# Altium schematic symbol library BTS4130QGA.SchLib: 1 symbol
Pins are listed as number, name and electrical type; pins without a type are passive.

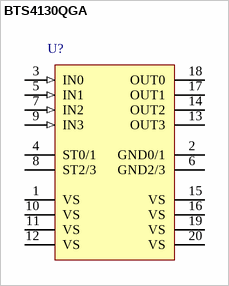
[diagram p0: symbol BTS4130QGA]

## BTS4130QGA
designator U?
Smart High-Side Power Switch, 4 Channels, 1.7 A Load Current, -40 to 150 degC, PG-DSO-20-32, Reel, Green; Manufacturer: Infineon; PartNumber: BTS4130QGA; Channels: 4; Green: TRUE; Group: Automotive Qualified; Load Current (typ): 1.7 A; Ptot (max): 1.4 W; Recommended Operating Voltage Max.: 20 V; Recommended Operating Voltage Min.: 5.5 V; RON @ 25degreesC: 130 mOhm; RON(max) @ 150degreesC: 260 mOhm; toff (max): 270 us; ton (max): 250 us
footprint INF-PG-DSO-20-32_N (SOP, 20-Leads, Body 12.7x7.5mm, Pitch 1.27mm, IPC Medium Density)
footprint INF-PG-DSO-20-32_L (SOP, 20-Leads, Body 12.7x7.5mm, Pitch 1.27mm, IPC High Density)
footprint INF-PG-DSO-20-32_M (SOP, 20-Leads, Body 12.7x7.5mm, Pitch 1.27mm, IPC Low Density)
pins: 1 VS (power) "Battery voltage; Design the wiring for the simultaneous maximum short circuit currents from channel 0 and 1 and also for low thermal resistance", 2 GND0/1 (power) "Ground; Ground connection for channel 0 and 1", 3 IN0 (in) "Input channel 0; Input signal for channel 0. Activate the channel in case of logic high level", 4 ST0/1 (oc) "Diagnostic feedback; of channel 0/1. Open drain.", 5 IN1 (in) "Input channel 1; Input signal for channel 1. Activate the channel in case of logic high level", 6 GND2/3 (power) "Ground; Ground connection for channel 2 and 3", 7 IN2 (in) "Input channel 2; Input signal for channel 2. Activate the channel in case of logic high level", 8 ST2/3 (oc) "Diagnostic feedback; of channel 2/3. Open drain.", 9 IN3 (in) "Input channel 3; Input signal for channel 3. Activate the channel in case of logic high level", 10 VS (power) "Battery voltage; Design the wiring for the simultaneous maximum short circuit currents from channel 0 and 1 and also for low thermal resistance", 11 VS (power) "Battery voltage; Design the wiring for the simultaneous maximum short circuit currents from channel 0 and 1 and also for low thermal resistance", 12 VS (power) "Battery voltage; Design the wiring for the simultaneous maximum short circuit currents from channel 0 and 1 and also for low thermal resistance", 13 OUT3 (power) "Output 3; Protected High side power output channel 3", 14 OUT2 (power) "Output 2; Protected High side power output channel 2", 15 VS (power) "Battery voltage; Design the wiring for the simultaneous maximum short circuit currents from channel 0 and 1 and also for low thermal resistance", 16 VS (power) "Battery voltage; Design the wiring for the simultaneous maximum short circuit currents from channel 0 and 1 and also for low thermal resistance", 17 OUT1 (power) "Output 1; Protected High side power output channel 1", 18 OUT0 (power) "Output 0; Protected High side power output channel 0", 19 VS (power) "Battery voltage; Design the wiring for the simultaneous maximum short circuit currents from channel 0 and 1 and also for low thermal resistance", 20 VS (power) "Battery voltage; Design the wiring for the simultaneous maximum short circuit currents from channel 0 and 1 and also for low thermal resistance"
